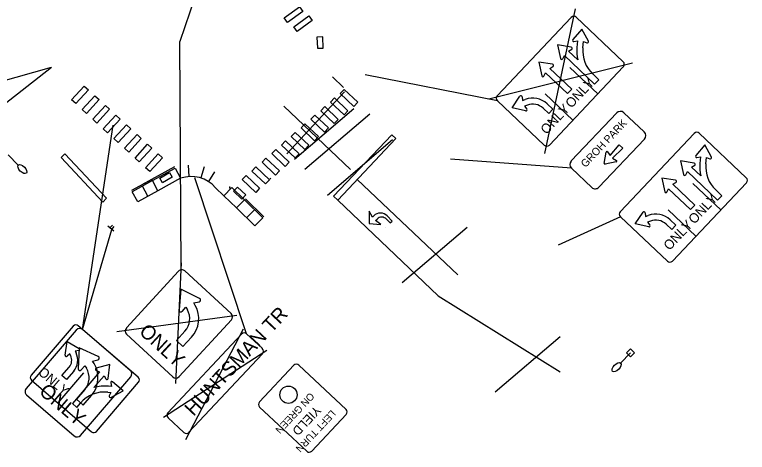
# Model space of a CAD drawing. Extents: x 1481212 to 1485683, y 378085 to 388655.
# Drawn here: x 1481389 to 1481644.2, y 378084.6 to 378237 of the extents above; entities that cross this region are included whole.
import ezdxf

# ---------------------------------------------------------------- set-up
doc = ezdxf.new("R2010")
doc.units = 0
for name, color, linetype in [('LT_X_Luminaires', 7, 'Continuous'), ('RS_Raster1', 7, 'Continuous'), ('RW_X_CL', 7, 'Continuous'), ('RW_X_CL_100_Bearings', 7, 'Continuous'), ('RW_X_CL_100_Curve_Data', 7, 'Continuous'), ('RW_X_CL_100_Distances', 7, 'Continuous'), ('RW_X_CL_500_Cardinal_Points', 7, 'Continuous'), ('RW_X_CL_500_Distances', 7, 'Continuous'), ('RW_X_CL_500_Stations', 7, 'Continuous'), ('SC_Scratch1', 7, 'Continuous'), ('SC_Scratch15', 7, 'Continuous'), ('SC_Scratch8', 7, 'Continuous'), ('SN_P_Signs', 7, 'Continuous')]:
    doc.layers.add(name, color=color, linetype=linetype)

msp = doc.modelspace()

# ---------------------------------------------------------------- linework, layer by layer
at = {"layer": 'LT_X_Luminaires'}
for p, q in [((1481386.69, 378188.18), (1481390.23, 378184.64)), ((1481603.52, 378119.27), (1481600.04, 378115.68))]:
    msp.add_line(p, q, dxfattribs=at)
msp.add_lwpolyline([(1481604.93, 378119.3), (1481603.54, 378117.86), (1481602.11, 378119.25), (1481603.5, 378120.69)], close=True, dxfattribs=at)
for centre, major_axis in [((1481391.64, 378183.23), (1.42, -1.41)), ((1481598.65, 378114.24), (-1.39, -1.44))]:
    msp.add_ellipse(centre, major_axis=major_axis, ratio=0.5, dxfattribs=at)
at = {"layer": 'RS_Raster1'}
msp.add_line((1481503.84, 378210.08), (1481483.72, 378188.52), dxfattribs=at)
for points in [[(1481488.13, 378239.72), (1481489.3, 378238.1), (1481484.04, 378234.28), (1481482.86, 378235.9)], [(1481491.43, 378236.55), (1481492.6, 378234.93), (1481487.34, 378231.12), (1481486.17, 378232.74)], [(1481413.19, 378212.15), (1481414.66, 378210.8), (1481410.27, 378206.01), (1481408.79, 378207.36)], [(1481502.38, 378209.52), (1481503.75, 378210.98), (1481508.47, 378206.51), (1481507.1, 378205.05)], [(1481416.87, 378208.77), (1481418.35, 378207.42), (1481413.95, 378202.63), (1481412.48, 378203.98)], [(1481498.98, 378206.54), (1481500.35, 378208), (1481505.07, 378203.53), (1481503.7, 378202.07)], [(1481420.56, 378205.39), (1481422.03, 378204.04), (1481417.63, 378199.25), (1481416.16, 378200.6)], [(1481495.58, 378203.56), (1481496.96, 378205.02), (1481501.68, 378200.55), (1481500.3, 378199.09)], [(1481424.24, 378202.01), (1481425.71, 378200.66), (1481421.32, 378195.87), (1481419.85, 378197.22)], [(1481492.18, 378200.59), (1481493.56, 378202.04), (1481498.28, 378197.57), (1481496.9, 378196.11)], [(1481427.92, 378198.63), (1481429.4, 378197.28), (1481425, 378192.49), (1481423.53, 378193.84)], [(1481488.72, 378197.55), (1481490.09, 378199), (1481494.81, 378194.53), (1481493.44, 378193.08)], [(1481431.61, 378195.25), (1481433.08, 378193.9), (1481428.69, 378189.11), (1481427.21, 378190.46)], [(1481485.32, 378194.57), (1481486.7, 378196.02), (1481491.41, 378191.55), (1481490.04, 378190.1)], [(1481481.92, 378191.59), (1481483.3, 378193.04), (1481488.02, 378188.57), (1481486.64, 378187.12)], [(1481435.29, 378191.87), (1481436.77, 378190.52), (1481432.37, 378185.73), (1481430.9, 378187.08)], [(1481478.53, 378188.61), (1481479.9, 378190.06), (1481484.62, 378185.59), (1481483.24, 378184.14)], [(1481438.98, 378188.49), (1481440.45, 378187.14), (1481436.06, 378182.35), (1481434.58, 378183.7)], [(1481475.13, 378185.63), (1481476.5, 378187.08), (1481481.22, 378182.61), (1481479.85, 378181.16)], [(1481471.61, 378182.53), (1481472.99, 378183.98), (1481477.71, 378179.51), (1481476.33, 378178.06)], [(1481468.21, 378179.55), (1481469.59, 378181), (1481474.31, 378176.53), (1481472.93, 378175.08)]]:
    msp.add_lwpolyline(points, close=True, dxfattribs=at)
at = {"layer": 'RW_X_CL'}
for p, q in [((1481463.64, 378176.69), (1481463.64, 378176.69)), ((1481463.74, 378176.81), (1481463.74, 378176.81)), ((1481463.78, 378176.56), (1481463.78, 378176.56)), ((1481463.87, 378176.96), (1481463.87, 378176.96)), ((1481463.89, 378176.68), (1481463.89, 378176.68)), ((1481463.9, 378176.46), (1481463.9, 378176.46)), ((1481464.01, 378176.58), (1481464.01, 378176.58)), ((1481464.02, 378176.83), (1481464.02, 378176.83)), ((1481464.14, 378176.72), (1481464.14, 378176.72))]:
    msp.add_line(p, q, dxfattribs=at)
for centre, radius in [((1481463.74, 378176.81), 0.0375), ((1481463.74, 378176.81), 0.0167), ((1481463.87, 378176.96), 0.0375), ((1481463.87, 378176.96), 0.0167), ((1481463.89, 378176.68), 0.0375), ((1481463.89, 378176.68), 0.0167), ((1481464.02, 378176.83), 0.0375), ((1481464.02, 378176.83), 0.0167)]:
    msp.add_circle(centre, radius, dxfattribs=at)
at = {"layer": 'RW_X_CL_100_Bearings'}
msp.add_line((1481508.3, 378179.59), (1481543.39, 378146.37), dxfattribs=at)
at = {"layer": 'RW_X_CL_100_Curve_Data'}
for p, q in [((1481586.48, 378232), (1481583.38, 378228.3)), ((1481588.83, 378227.78), (1481586.48, 378232)), ((1481578.09, 378226.46), (1481579.1, 378221.74)), ((1481582.86, 378225.72), (1481578.09, 378226.46)), ((1481583.78, 378227.62), (1481585.04, 378227.89)), ((1481585.04, 378227.89), (1481584.83, 378225.6)), ((1481586.9, 378225.41), (1481587.12, 378227.69)), ((1481587.12, 378227.69), (1481588.3, 378227.19)), ((1481581.88, 378224.31), (1481583, 378224.94)), ((1481585.15, 378221.22), (1481581.88, 378224.31)), ((1481579.88, 378221.64), (1481580.45, 378222.8)), ((1481580.45, 378222.8), (1481590.99, 378212.82)), ((1481383.18, 378213.53), (1481401.74, 378218.69)), ((1481571.55, 378220.46), (1481572.56, 378215.73)), ((1481576.32, 378219.71), (1481571.55, 378220.46)), ((1481575.34, 378218.31), (1481576.46, 378218.94)), ((1481583.01, 378211.05), (1481575.34, 378218.31)), ((1481582.4, 378218.59), (1481592.08, 378209.43)), ((1481557.11, 378207.02), (1481511.05, 378216.01)), ((1481573.34, 378215.64), (1481573.91, 378216.8)), ((1481573.91, 378216.8), (1481581.58, 378209.54)), ((1481592.42, 378214.34), (1481590.31, 378216.34)), ((1481590.99, 378212.82), (1481592.42, 378214.34)), ((1481581.58, 378209.54), (1481583.01, 378211.05)), ((1481562.27, 378204.58), (1481564.99, 378208.57)), ((1481565.75, 378208.36), (1481565.84, 378207.08)), ((1481573.73, 378209.43), (1481583.42, 378200.27)), ((1481565.84, 378207.08), (1481566.82, 378207.46)), ((1481567.57, 378205.51), (1481566.59, 378205.13)), ((1481574.46, 378205.95), (1481576.43, 378204.09)), ((1481566.97, 378203.46), (1481562.27, 378204.58)), ((1481566.59, 378205.13), (1481567.39, 378204.12)), ((1481575, 378202.58), (1481573.03, 378204.44)), ((1481576.43, 378204.09), (1481575, 378202.58)), ((1481596.35, 378187.92), (1481599.58, 378191.64)), ((1481600.79, 378190.49), (1481597.26, 378187.06)), ((1481599.58, 378191.64), (1481600.79, 378190.49)), ((1481629.33, 378191.62), (1481626.23, 378187.91)), ((1481631.69, 378187.4), (1481629.33, 378191.62)), ((1481594.37, 378185.23), (1481594.98, 378189.13)), ((1481595.47, 378189.24), (1481596.35, 378187.92)), ((1481597.52, 378188.03), (1481597.52, 378188.03)), ((1481626.64, 378187.24), (1481627.9, 378187.51)), ((1481627.9, 378187.51), (1481627.68, 378185.22)), ((1481582.92, 378183.55), (1481540.81, 378186.67)), ((1481598.54, 378185.76), (1481594.69, 378184.93)), ((1481597.26, 378187.06), (1481598.62, 378186.26)), ((1481620.94, 378186.08), (1481621.95, 378181.35)), ((1481625.72, 378185.33), (1481620.94, 378186.08)), ((1481629.76, 378185.02), (1481629.97, 378187.31)), ((1481629.97, 378187.31), (1481631.16, 378186.81)), ((1481622.74, 378181.26), (1481623.3, 378182.42)), ((1481623.3, 378182.42), (1481633.85, 378172.44)), ((1481624.73, 378183.93), (1481625.86, 378184.56)), ((1481628.01, 378180.83), (1481624.73, 378183.93)), ((1481469.76, 378125.84), (1481451.71, 378180.21)), ((1481614.4, 378180.08), (1481615.42, 378175.35)), ((1481619.18, 378179.33), (1481614.4, 378180.08)), ((1481618.19, 378177.93), (1481619.32, 378178.56)), ((1481625.87, 378170.67), (1481618.19, 378177.93)), ((1481625.25, 378178.21), (1481634.94, 378169.05)), ((1481616.2, 378175.25), (1481616.76, 378176.41)), ((1481616.76, 378176.41), (1481624.44, 378169.16)), ((1481635.28, 378173.95), (1481633.16, 378175.96)), ((1481633.85, 378172.44), (1481635.28, 378173.95)), ((1481624.44, 378169.16), (1481625.87, 378170.67)), ((1481605.12, 378164.2), (1481607.85, 378168.19)), ((1481608.61, 378167.98), (1481608.69, 378166.69)), ((1481608.69, 378166.69), (1481609.68, 378167.07)), ((1481616.59, 378169.05), (1481626.28, 378159.89)), ((1481599.97, 378166.63), (1481578.32, 378156.69)), ((1481610.43, 378165.13), (1481609.44, 378164.75)), ((1481609.44, 378164.75), (1481610.25, 378163.74)), ((1481617.31, 378165.57), (1481619.28, 378163.71)), ((1481609.82, 378163.08), (1481605.12, 378164.2)), ((1481617.85, 378162.19), (1481615.88, 378164.06)), ((1481619.28, 378163.71), (1481617.85, 378162.19))]:
    msp.add_line(p, q, dxfattribs=at)
for points in [[(1481582.83, 378236.03), (1481557.06, 378208.78)], [(1481600.94, 378220.62), (1481584.6, 378236.08)], [(1481575.23, 378191.61), (1481600.99, 378218.85)], [(1481557.11, 378207.02), (1481573.46, 378191.56)], [(1481598.67, 378202.78), (1481582.85, 378186.05)], [(1481608.25, 378196.16), (1481601.18, 378202.85)], [(1481625.68, 378195.65), (1481599.92, 378168.4)], [(1481643.8, 378180.24), (1481627.45, 378195.69)], [(1481592.5, 378176.92), (1481608.32, 378193.65)], [(1481582.92, 378183.55), (1481590, 378176.85)], [(1481618.08, 378151.22), (1481643.85, 378178.47)], [(1481599.97, 378166.63), (1481616.32, 378151.17)], [(1481467.99, 378125.78), (1481442.37, 378098.4)], [(1481469.76, 378125.84), (1481475.24, 378120.71)], [(1481449.67, 378091.57), (1481475.29, 378118.95)], [(1481442.43, 378096.63), (1481447.91, 378091.51)]]:
    msp.add_lwpolyline(points, dxfattribs=at)
for centre, radius, start, end in [((1481583.74, 378235.17), 1.25, 46.6, 136.6), ((1481583.7, 378228.03), 0.417, 140.0694, 281.9475), ((1481582.8, 378225.31), 0.417, 299.2382, 81.1163), ((1481588.47, 378227.58), 0.417, 247.2239, 29.102), ((1481597.89, 378224.37), 13.12, 174.5857, 193.8745), ((1481597.89, 378224.37), 11.04, 174.5857, 226.6), ((1481579.51, 378221.82), 0.417, 192.0837, 333.9618), ((1481600.09, 378219.71), 1.25, 316.6, 46.6), ((1481576.26, 378219.3), 0.417, 299.2382, 81.1163), ((1481572.97, 378215.82), 0.417, 192.0837, 333.9618), ((1481557.97, 378207.92), 1.25, 136.6, 226.6), ((1481565.34, 378208.34), 0.417, 3.7555, 145.6336), ((1481569.45, 378200.65), 7.29, 46.6, 111.1173), ((1481569.45, 378200.65), 5.21, 46.6, 111.1173), ((1481567.06, 378203.87), 0.417, 256.601, 38.4791), ((1481599.96, 378201.57), 1.77, 46.6, 136.6), ((1481607.04, 378194.87), 1.77, 316.6, 46.6), ((1481626.59, 378194.79), 1.25, 46.6, 136.6), ((1481574.32, 378192.46), 1.25, 226.6, 316.6), ((1481595.25, 378189.09), 0.27, 33.6238, 171.0971), ((1481626.55, 378187.65), 0.417, 140.0694, 281.9475), ((1481584.14, 378184.83), 1.77, 136.6, 226.6), ((1481594.64, 378185.2), 0.27, 172.5064, 280.6936), ((1481598.49, 378186.02), 0.27, 282.1029, 59.5762), ((1481625.65, 378184.92), 0.417, 299.2382, 81.1163), ((1481640.75, 378183.98), 13.12, 174.5857, 193.8745), ((1481640.75, 378183.98), 11.04, 174.5857, 226.6), ((1481631.32, 378187.19), 0.417, 247.2239, 29.102), ((1481622.36, 378181.44), 0.417, 192.0837, 333.9618), ((1481642.94, 378179.33), 1.25, 316.6, 46.6), ((1481619.12, 378178.92), 0.417, 299.2382, 81.1163), ((1481591.21, 378178.14), 1.77, 226.6, 316.6), ((1481615.82, 378175.44), 0.417, 192.0837, 333.9618), ((1481600.83, 378167.54), 1.25, 136.6, 226.6), ((1481608.19, 378167.95), 0.417, 3.7555, 145.6336), ((1481612.3, 378160.27), 7.29, 46.6, 111.1173), ((1481612.3, 378160.27), 5.21, 46.6, 111.1173), ((1481609.92, 378163.48), 0.417, 256.601, 38.4791), ((1481617.18, 378152.08), 1.25, 226.6, 316.6), ((1481468.91, 378124.93), 1.25, 46.9, 136.9), ((1481474.38, 378119.8), 1.25, 316.9, 46.9), ((1481443.28, 378097.55), 1.25, 136.9, 226.9), ((1481448.76, 378092.42), 1.25, 226.9, 316.9)]:
    msp.add_arc(centre, radius, start, end, dxfattribs=at)
at = {"layer": 'RW_X_CL_100_Distances'}
for p, q in [((1481512.49, 378168.56), (1481512.46, 378164.29)), ((1481512.49, 378168.56), (1481512.49, 378168.56)), ((1481513.58, 378166.49), (1481512.49, 378168.56)), ((1481514.05, 378166.95), (1481513.58, 378166.49)), ((1481514.69, 378165.34), (1481515.2, 378165.83)), ((1481516.49, 378163.97), (1481514.69, 378165.34)), ((1481518.44, 378165.79), (1481519.74, 378164.46)), ((1481520.46, 378165.15), (1481518.73, 378166.93)), ((1481519.74, 378164.46), (1481520.46, 378165.15)), ((1481512.46, 378164.29), (1481516.49, 378163.97)), ((1481518.07, 378162.83), (1481518.07, 378162.83))]:
    msp.add_line(p, q, dxfattribs=at)
for centre, radius, end in [((1481516.38, 378164.64), 3.28, 135.1627), ((1481516.8, 378164.19), 2.3, 134.2542)]:
    msp.add_arc(centre, radius, 44.2542, end, dxfattribs=at)
at = {"layer": 'RW_X_CL_500_Cardinal_Points'}
for p, q in [((1481499.64, 378215.37), (1481503.47, 378211.61)), ((1481444.63, 378183.98), (1481433.21, 378177.71)), ((1481436.95, 378179.2), (1481444.84, 378183.53)), ((1481444.84, 378183.53), (1481446.77, 378180.02)), ((1481449.39, 378184.59), (1481449.68, 378180.63)), ((1481454.95, 378183.96), (1481453.77, 378180.16)), ((1481446.77, 378180.02), (1481438.88, 378175.69)), ((1481458.62, 378182.28), (1481456.47, 378178.91)), ((1481436.71, 378179.63), (1481429.7, 378175.78)), ((1481436.95, 378179.2), (1481429.94, 378175.35)), ((1481435.37, 378173.77), (1481433.45, 378177.27)), ((1481438.88, 378175.69), (1481436.95, 378179.2)), ((1481431.87, 378171.84), (1481429.94, 378175.35)), ((1481438.88, 378175.69), (1481431.87, 378171.84)), ((1481458.98, 378176.7), (1481461.87, 378173.9)), ((1481464.65, 378176.77), (1481461.87, 378173.9)), ((1481468.97, 378172.57), (1481464.65, 378176.77)), ((1481461.87, 378173.9), (1481466.19, 378169.7)), ((1481466.19, 378169.7), (1481468.97, 378172.57)), ((1481468.97, 378172.57), (1481475.43, 378166.29)), ((1481469.32, 378172.92), (1481475.78, 378166.65)), ((1481466.19, 378169.7), (1481472.65, 378163.43)), ((1481469.78, 378166.22), (1481472.56, 378169.08)), ((1481472.65, 378163.43), (1481475.43, 378166.29))]:
    msp.add_line(p, q, dxfattribs=at)
for points in [[(1481496.27, 378229.28), (1481494.24, 378229.19), (1481494.41, 378225.28), (1481496.42, 378225.38)], [(1481443.87, 378180.37), (1481440.51, 378178.4), (1481439.51, 378180.03), (1481442.95, 378182.06)], [(1481469.49, 378174.22), (1481468.11, 378172.8), (1481465.23, 378175.51), (1481466.59, 378176.92)]]:
    msp.add_lwpolyline(points, close=True, dxfattribs=at)
msp.add_arc((1481450.47, 378169.52), 11.14, 40.169, 109.445, dxfattribs=at)
at = {"layer": 'RW_X_CL_500_Distances'}
for p, q in [((1481536.48, 378139.06), (1481501.49, 378172.39)), ((1481536.51, 378139.05), (1481578.99, 378112.69))]:
    msp.add_line(p, q, dxfattribs=at)
at = {"layer": 'RW_X_CL_500_Stations'}
for p, q in [((1481520.38, 378195.19), (1481500.03, 378173.77)), ((1481521.78, 378193.86), (1481520.38, 378195.19)), ((1481501.49, 378172.39), (1481521.78, 378193.86)), ((1481500.03, 378173.77), (1481501.49, 378172.39))]:
    msp.add_line(p, q, dxfattribs=at)
msp.add_lwpolyline([(1481405.17, 378187.24), (1481406.48, 378188.57), (1481421, 378173.12), (1481419.68, 378171.74)], close=True, dxfattribs=at)
at = {"layer": 'SC_Scratch1'}
for p, q in [((1481486.39, 378186.65), (1481507.08, 378204.27)), ((1481490.04, 378183.2), (1481512.7, 378202.49)), ((1481497.99, 378174.2), (1481520.64, 378193.49)), ((1481523.92, 378143.74), (1481546.57, 378163.03)), ((1481556.32, 378105.67), (1481578.98, 378124.95))]:
    msp.add_line(p, q, dxfattribs=at)
at = {"layer": 'SC_Scratch15'}
for p, q in [((1481484.35, 378340.02), (1481446.53, 378227.66)), ((1481446.94, 378148.13), (1481446.53, 378227.66)), ((1481347.25, 378176.05), (1481401.74, 378218.69)), ((1481505.98, 378183.03), (1481482.74, 378205.09)), ((1481412.65, 378127.36), (1481423.33, 378198.56)), ((1481477.87, 378179.68), (1481478.21, 378180.04)), ((1481445.14, 378108.57), (1481447.05, 378150.55)), ((1481446.86, 378141.43), (1481446.24, 378134.18)), ((1481453.39, 378138.22), (1481446.86, 378141.43)), ((1481451.36, 378136.65), (1481453.25, 378137.05)), ((1481451.85, 378135.78), (1481451.36, 378136.65)), ((1481447.32, 378133.7), (1481448.64, 378135.11)), ((1481448.64, 378135.11), (1481449.13, 378134.25)), ((1481466.41, 378132.28), (1481424.6, 378126.54)), ((1481448.26, 378126.81), (1481445.3, 378123.6)), ((1481445.3, 378123.6), (1481447.6, 378121.48)), ((1481447.6, 378121.48), (1481450.56, 378124.69)), ((1481411.43, 378120.99), (1481411.07, 378113.72)), ((1481418.07, 378118.02), (1481411.43, 378120.99)), ((1481416.1, 378116.37), (1481417.97, 378116.84)), ((1481416.62, 378115.53), (1481416.1, 378116.37)), ((1481412.16, 378113.28), (1481413.44, 378114.74)), ((1481413.44, 378114.74), (1481413.95, 378113.89)), ((1481413.36, 378106.43), (1481410.51, 378103.11)), ((1481412.88, 378101.08), (1481415.73, 378104.4)), ((1481410.51, 378103.11), (1481412.88, 378101.08))]:
    msp.add_line(p, q, dxfattribs=at)
for points in [[(1481446.09, 378147.66), (1481427.87, 378127.9)], [(1481464.38, 378132.92), (1481448.3, 378147.75)], [(1481446.25, 378110.96), (1481464.47, 378130.71)], [(1481410.44, 378127.19), (1481392.94, 378106.79)], [(1481429.25, 378113.12), (1481412.65, 378127.36)], [(1481427.96, 378125.7), (1481444.04, 378110.87)], [(1481474.24, 378102.14), (1481486.21, 378114.9)], [(1481487.98, 378114.96), (1481504.39, 378099.56)], [(1481411.92, 378090.51), (1481429.42, 378110.91)], [(1481393.11, 378104.59), (1481409.71, 378090.35)], [(1481490.7, 378084.98), (1481474.29, 378100.37)], [(1481504.44, 378097.8), (1481492.47, 378085.03)]]:
    msp.add_lwpolyline(points, dxfattribs=at)
msp.add_circle((1481484.34, 378104.66), 3, dxfattribs=at)
for centre, radius, start, end in [((1481447.24, 378146.6), 1.56, 47.3195, 137.3195), ((1481453.12, 378137.66), 0.625, 282.1131, 63.8849), ((1481446.86, 378134.13), 0.625, 175.0738, 316.8456), ((1481443.59, 378131.12), 6.35, 317.3195, 29.4582), ((1481443.59, 378131.12), 9.48, 317.3195, 29.4621), ((1481463.32, 378131.77), 1.56, 317.3195, 47.3195), ((1481411.63, 378126.17), 1.56, 49.3749, 139.3749), ((1481429.02, 378126.84), 1.56, 137.3195, 227.3195), ((1481417.82, 378117.45), 0.625, 284.1684, 65.9402), ((1481411.69, 378113.69), 0.625, 177.1291, 318.9009), ((1481408.54, 378110.57), 6.35, 319.3749, 31.5136), ((1481408.54, 378110.57), 9.48, 319.3749, 31.5174), ((1481487.12, 378114.05), 1.25, 46.8304, 136.8304), ((1481428.23, 378111.93), 1.56, 319.3749, 49.3749), ((1481445.1, 378112.02), 1.56, 227.3195, 317.3195), ((1481394.13, 378105.77), 1.56, 139.3749, 229.3749), ((1481475.15, 378101.28), 1.25, 136.8304, 226.8304), ((1481503.53, 378098.65), 1.25, 316.8304, 46.8304), ((1481410.73, 378091.53), 1.56, 229.3749, 319.3749), ((1481491.56, 378085.89), 1.25, 226.8304, 316.8304)]:
    msp.add_arc(centre, radius, start, end, dxfattribs=at)
at = {"layer": 'SC_Scratch8'}
for p, q in [((1481412.65, 378127.36), (1481422.76, 378162.2)), ((1481423.47, 378161.56), (1481421.44, 378163.38)), ((1481422.15, 378162.75), (1481423.06, 378163.76)), ((1481422.46, 378162.47), (1481422.46, 378162.47)), ((1481422.46, 378162.47), (1481422.46, 378162.47)), ((1481422.76, 378162.2), (1481423.67, 378163.21)), ((1481406.54, 378118.41), (1481407.26, 378123.19)), ((1481407.26, 378123.19), (1481411.47, 378120.81)), ((1481408.17, 378118.93), (1481407.24, 378118.05)), ((1481408.47, 378118.31), (1481408.17, 378118.93)), ((1481411.32, 378120.03), (1481410.05, 378119.84)), ((1481410.05, 378119.84), (1481410.35, 378119.22)), ((1481405.44, 378111.31), (1481407.95, 378114.23)), ((1481422.06, 378115.17), (1481417.39, 378113.93)), ((1481421.54, 378110.36), (1481422.06, 378115.17)), ((1481412.97, 378112.25), (1481404.02, 378101.82)), ((1481407.02, 378109.95), (1481405.44, 378111.31)), ((1481409.53, 378112.88), (1481407.02, 378109.95)), ((1481418.51, 378112.63), (1481409.06, 378101.61)), ((1481416.55, 378107.14), (1481420.09, 378111.27)), ((1481417.33, 378113.14), (1481418.51, 378112.63)), ((1481420.09, 378111.27), (1481420.78, 378110.18)), ((1481422.41, 378108.78), (1481422.67, 378107.52)), ((1481426.77, 378106.05), (1481423.09, 378109.18)), ((1481422.67, 378107.52), (1481421.66, 378107.62)), ((1481422.52, 378103.73), (1481426.77, 378106.05)), ((1481421.45, 378105.55), (1481422.45, 378105.45)), ((1481422.45, 378105.45), (1481421.94, 378104.26)), ((1481409.06, 378101.61), (1481410.64, 378100.26)), ((1481410.64, 378100.26), (1481411.93, 378101.76))]:
    msp.add_line(p, q, dxfattribs=at)
for points in [[(1481409.36, 378128.53), (1481394.71, 378111.45)], [(1481432, 378110.75), (1481411.13, 378128.66)], [(1481394.85, 378109.69), (1481415.72, 378091.78)], [(1481417.48, 378091.91), (1481432.13, 378108.99)]]:
    msp.add_lwpolyline(points, dxfattribs=at)
for centre, radius, start, end in [((1481410.31, 378127.71), 1.25, 49.3749, 139.3749), ((1481405.1, 378116.67), 5.83, 319.3749, 25.9089), ((1481411.26, 378120.45), 0.417, 278.547, 60.4251), ((1481406.95, 378118.35), 0.417, 171.3926, 313.2707), ((1481405.1, 378116.67), 3.75, 319.3749, 25.9089), ((1481417.49, 378113.52), 0.417, 104.8586, 246.7367), ((1481395.66, 378110.63), 1.25, 139.3749, 229.3749), ((1481421.13, 378110.4), 0.417, 212.013, 353.8911), ((1481422.82, 378108.87), 0.417, 49.5607, 191.4388), ((1481431.19, 378109.81), 1.25, 319.3749, 49.3749), ((1481420.31, 378094.57), 13.13, 84.077, 106.6493), ((1481420.31, 378094.57), 11.04, 84.077, 139.3749), ((1481422.32, 378104.1), 0.417, 156.7151, 298.5932), ((1481416.54, 378092.73), 1.25, 229.3749, 319.3749)]:
    msp.add_arc(centre, radius, start, end, dxfattribs=at)
at = {"layer": 'SN_P_Signs'}
for p, q in [((1481573.66, 378188.63), (1481584.3, 378239.04)), ((1481604.19, 378220.14), (1481554.17, 378207.59)), ((1481468.52, 378127.45), (1481448.47, 378089)), ((1481440.82, 378096.81), (1481476.81, 378120.16))]:
    msp.add_line(p, q, dxfattribs=at)

# ---------------------------------------------------------------- texts
at = {"layer": 'RW_X_CL_100_Curve_Data'}
for s, height, rotation, p in [('ONLY', 3.333, 46.6, (1481582.87, 378204.23)), ('ONLY', 3.333, 46.6, (1481574.21, 378195.07)), ('GROH PARK', 2.657, 46.6, (1481587.81, 378183.56)), ('ONLY', 3.333, 46.6, (1481625.72, 378163.85)), ('ONLY', 3.333, 46.6, (1481617.06, 378154.69)), ('      HUNTSMAN TR', 5, 46.9, (1481443.65, 378088.79))]:
    msp.add_text(s, height=height, rotation=rotation, dxfattribs=at).set_placement(p)
at = {"layer": 'SC_Scratch15'}
for s, height, rotation, p in [('ONLY', 5, 317.3195, (1481431.99, 378126.23)), ('ONLY', 5, 319.3749, (1481397.12, 378105.27)), ('ON GREEN', 2.503, 226.8304, (1481491.8, 378105.61)), ('YIELD', 3.128, 226.8304, (1481493.67, 378101.06)), ('LEFT TURN', 2.503, 226.8304, (1481499.25, 378099.54))]:
    msp.add_text(s, height=height, rotation=rotation, dxfattribs=at).set_placement(p)
at = {"layer": 'SC_Scratch8'}
msp.add_text('ONLY', height=3.333, rotation=319.3749, dxfattribs=at).set_placement((1481396.86, 378112.08))

doc.saveas('drawing.dxf')
